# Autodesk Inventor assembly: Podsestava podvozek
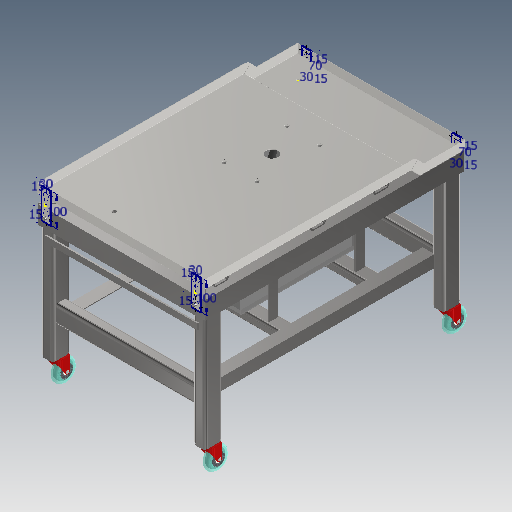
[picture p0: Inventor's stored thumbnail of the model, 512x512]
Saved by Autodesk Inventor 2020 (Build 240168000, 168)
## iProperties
Created: 2025-04
Part Number: Podsestava podvozek
Document SubType Name: Assembly
Designer: doma
Author: doma
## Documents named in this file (10)
- C:\Users\doma\Desktop\Pásovka záloha\Workgroups\NotInProject\Podsestava podvozek.iam
- C:\Users\doma\Desktop\Pásovka záloha\Workgroups\NotInProject\Svařenec vana.iam
- C:\Users\doma\Desktop\Pásovka záloha\Workgroups\NotInProject\Svařenec podvozek.iam
- C:\Users\doma\Desktop\Pásovka záloha\Workgroups\NotInProject\Podsestava chlazení.iam
- C:\Users\doma\Desktop\Pásovka záloha\Workgroups\NotInProject\Hadice odpadní.ipt
- C:\Users\doma\Documents\Inventor\Content Center Files\R2020\cs-CZ\CSN 02 1741\CSN 02 1741 - 6.ipt
- C:\Users\doma\Documents\Inventor\Content Center Files\R2020\cs-CZ\ISO 4762(2)\ISO 4762 - M6 x 10ISO.ipt
- C:\Users\doma\Desktop\Pásovka záloha\Workgroups\NotInProject\Kolečko.ipt
- C:\Users\doma\Documents\Inventor\Content Center Files\R2020\cs-CZ\ISO 4762(2)\ISO 4762 - M5 x 25ISO.ipt
- C:\Users\doma\Desktop\Pásovka záloha\Workgroups\NotInProject\Záslepka M16.ipt
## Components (22 placed, 9 different names)
1. Svařenec podvozek:1 [sub-assembly] — Proti sobě:15, Proti sobě:16, Proti sobě:17
2. Podsestava chlazení:1 [sub-assembly]
3. Hadice odpadní:1
4. CSN 02 1741 6:1 — Stejný směr:20, Proti sobě:18
5. CSN 02 1741 6:2 — Stejný směr:20
6. CSN 02 1741 6:3 — Stejný směr:21
7. CSN 02 1741 6:4 — Stejný směr:21, Proti sobě:21
8. ISO 4762 M6 x 10:1 — Proti sobě:19
9. ISO 4762 M6 x 10:2 — Proti sobě:20
10. ISO 4762 M6 x 10:3 — Proti sobě:23
11. ISO 4762 M6 x 10:4 — Proti sobě:22
12. Kolečko:1
13. Kolečko:2
14. Kolečko:3
15. Kolečko:4
16. ISO 4762 M5 x 25:1
17. ISO 4762 M5 x 25:2
18. Záslepka M16:1
19. Záslepka M16:2
20. Záslepka M16:3
21. Záslepka M16:4
22. Svařenec vana:2 [sub-assembly] — Proti sobě:15, Proti sobě:16, Proti sobě:17, Proti sobě:18, Proti sobě:19, Proti sobě:20, Proti sobě:21, Proti sobě:22, Proti sobě:23
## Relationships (11: Mate 9, Flush 2)
- Proti sobě:15 [Mate]: Svařenec podvozek:1 ↔ Svařenec vana:2
- Proti sobě:16 [Mate]: Svařenec podvozek:1 ↔ Svařenec vana:2
- Proti sobě:17 [Mate]: Svařenec podvozek:1 ↔ Svařenec vana:2
- Stejný směr:20 [Flush]: CSN 02 1741 6:1 ↔ CSN 02 1741 6:2
- Proti sobě:18 [Mate]: CSN 02 1741 6:1 ↔ Svařenec vana:2
- Proti sobě:19 [Mate]: ISO 4762 M6 x 10:1 ↔ Svařenec vana:2
- Proti sobě:20 [Mate]: ISO 4762 M6 x 10:2 ↔ Svařenec vana:2
- Stejný směr:21 [Flush]: CSN 02 1741 6:3 ↔ CSN 02 1741 6:4
- Proti sobě:21 [Mate]: CSN 02 1741 6:4 ↔ Svařenec vana:2
- Proti sobě:22 [Mate]: ISO 4762 M6 x 10:4 ↔ Svařenec vana:2
- Proti sobě:23 [Mate]: ISO 4762 M6 x 10:3 ↔ Svařenec vana:2
## Named parameters: d757_d76 = 0, d763_d58 = 0
